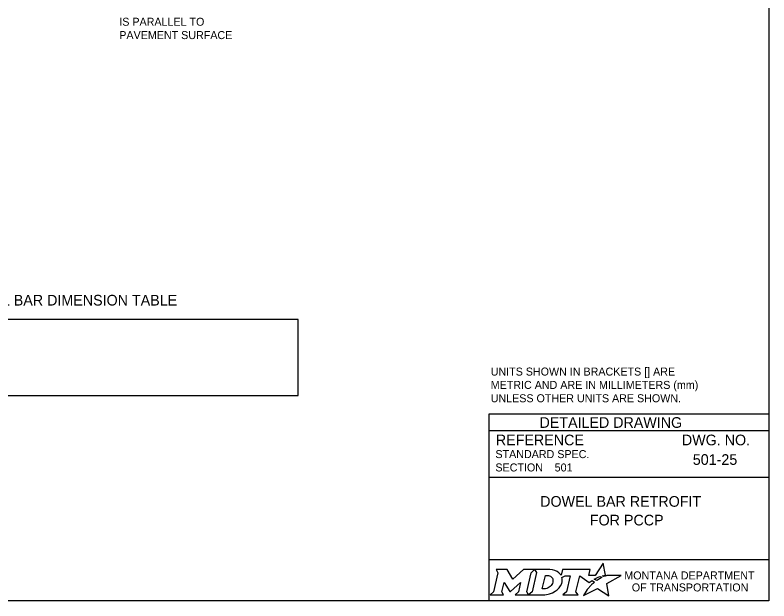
# Model space of a CAD drawing. Extents: x 49991.4 to 50021, y 49987.6 to 50011.4.
# Drawn here: x 50011.1 to 50016.75, y 49987.8 to 49992.19 of the extents above; entities that cross this region are included whole.
import ezdxf

# ---------------------------------------------------------------- set-up
doc = ezdxf.new("R2010")
doc.units = 0
for name, color, linetype in [('Default', 7, 'Continuous'), ('Level 1', 7, 'Continuous'), ('Level 2', 7, 'Continuous'), ('Level 5', 7, 'Continuous')]:
    doc.layers.add(name, color=color, linetype=linetype)

msp = doc.modelspace()

# ---------------------------------------------------------------- linework, layer by layer
at = {"layer": 'Default'}
for points in [[(50015.5126, 49987.9811), (50015.5023, 49987.9867), (50015.5139, 49987.9895), (50015.5255, 49987.9915), (50015.5081, 49988.0816), (50015.4486, 49987.9903), (50015.4013, 49987.9896), (50015.4116, 49988.0337), (50015.2024, 49988.0338), (50015.1923, 49987.9913), (50015.1865, 49987.9996)], [(50014.7056, 49988.0338), (50014.7197, 49988.0104), (50014.6862, 49987.8671), (50014.6605, 49987.8446), (50014.7621, 49987.8446), (50014.7486, 49987.8674), (50014.7648, 49987.9375), (50014.8085, 49987.8685), (50014.8138, 49987.8685), (50014.8889, 49987.938), (50014.8725, 49987.8669), (50014.8478, 49987.8449), (50014.9494, 49987.8449), (50014.9356, 49987.8682), (50014.9688, 49988.0106)], [(50014.9688, 49988.0106), (50014.9941, 49988.0338), (50014.9117, 49988.0338), (50014.8321, 49987.9608), (50014.7876, 49988.0335), (50014.7056, 49988.0338)], [(50015.1077, 49988.0338), (50014.9941, 49988.0338), (50015.0088, 49988.0109), (50014.9749, 49987.8671), (50014.9494, 49987.8449), (50015.06, 49987.8449)], [(50015.1317, 49987.9471), (50015.1305, 49987.939), (50015.1273, 49987.9297), (50015.1231, 49987.9215), (50015.1175, 49987.914), (50015.111, 49987.9071), (50015.1031, 49987.9008), (50015.0948, 49987.8961), (50015.0857, 49987.8922), (50015.0766, 49987.8899), (50015.0674, 49987.889), (50015.0515, 49987.889), (50015.0751, 49987.989), (50015.0911, 49987.989), (50015.0987, 49987.9884), (50015.1063, 49987.9865), (50015.1129, 49987.9835), (50015.119, 49987.9793), (50015.1238, 49987.9743), (50015.1275, 49987.9683), (50015.1302, 49987.9621), (50015.1318, 49987.9547), (50015.1318, 49987.9517), (50015.1317, 49987.9471)], [(50015.1991, 49987.9747), (50015.2237, 49987.9878), (50015.2606, 49987.9878), (50015.232, 49987.8673), (50015.2045, 49987.8446), (50015.3207, 49987.8446), (50015.3037, 49987.8675), (50015.3319, 49987.9877), (50015.4032, 49987.936), (50015.4243, 49987.9511), (50015.444, 49987.9402)], [(50015.3882, 49987.8843), (50015.3729, 49987.8599), (50015.3682, 49987.8524), (50015.3624, 49987.8438), (50015.3601, 49987.8395), (50015.4654, 49987.8926), (50015.5493, 49987.8375), (50015.5362, 49987.9302), (50015.6431, 49987.9886), (50015.5938, 49987.9894), (50015.5637, 49987.9898), (50015.5429, 49987.9901), (50015.5361, 49987.9886), (50015.5312, 49987.9874), (50015.5228, 49987.9851), (50015.5126, 49987.9811)], [(50015.4622, 49987.9535), (50015.4598, 49987.9518), (50015.4415, 49987.9614), (50015.4518, 49987.9671), (50015.4559, 49987.9693), (50015.4645, 49987.9733), (50015.4702, 49987.9759), (50015.4781, 49987.9789), (50015.4854, 49987.9816), (50015.4972, 49987.9742), (50015.4932, 49987.9721), (50015.4886, 49987.9696), (50015.4844, 49987.9674), (50015.4794, 49987.9645), (50015.4775, 49987.9634), (50015.4748, 49987.9618), (50015.4723, 49987.9604), (50015.47, 49987.9588), (50015.4674, 49987.957), (50015.4647, 49987.9552), (50015.4622, 49987.9535)], [(50015.1057, 49987.8522), (50015.1141, 49987.8548), (50015.1271, 49987.8602), (50015.1475, 49987.8712)], [(50015.4021, 49987.9004), (50015.4021, 49987.9004)]]:
    msp.add_lwpolyline(points, dxfattribs=at)
for centre, radius, start, end in [((50015.1308, 49987.9554), 0.0709, 339.5329, 15.8582), ((50015.0868, 49987.9727), 0.1183, 300.9103, 339.1383)]:
    msp.add_arc(centre, radius, start, end, dxfattribs=at)
for centre, major_axis, ratio, start_param, end_param in [((50015.1056, 49987.9864), (0.0834, -0.0037), 0.568097, 0.61298, 1.570796), ((50015.1612, 49987.9937), (0.0361, -0.0295), 0.469099, 1.225588, 1.570796), ((50015.4119, 49987.9106), (-0.0098, -0.0102), 0.016458, 3.141593, 6.279097), ((50015.4329, 49987.9305), (-0.0112, -0.0097), 0.021651, 3.157348, 6.283185), ((50015.3952, 49987.8923), (-0.00694, -0.00806), 0.008222, 0, 3.137361), ((50015.0603, 49987.9932), (0, 0.1484), 0.987302, 3.139398, 3.456847)]:
    msp.add_ellipse(centre, major_axis=major_axis, ratio=ratio, start_param=start_param, end_param=end_param, dxfattribs=at)
at = {"layer": 'Level 1'}
msp.add_lwpolyline([(49999.3835, 49998.9992), (50016.7501, 49998.9992), (50016.7501, 49987.7988), (49999.3835, 49987.7988)], close=True, dxfattribs=at)
at = {"layer": 'Level 2'}
msp.add_lwpolyline([(50009.9559, 49989.3382), (50013.2227, 49989.3382), (50013.2227, 49989.9081), (50009.9559, 49989.9081)], close=True, dxfattribs=at)
at = {"layer": 'Level 5'}
for p, q in [((50016.7501, 49989.1988), (50014.6501, 49989.1988)), ((50014.6501, 49989.1988), (50014.6501, 49987.7988)), ((50016.7501, 49989.0738), (50014.6501, 49989.0738)), ((50016.7501, 49988.7238), (50014.6501, 49988.7238)), ((50016.7501, 49988.1057), (50014.6501, 49988.1057))]:
    msp.add_line(p, q, dxfattribs=at)

# ---------------------------------------------------------------- texts
at = {"layer": 'Default'}
for s, p in [('MONTANA DEPARTMENT', (50015.6663, 49987.96)), ('OF TRANSPORTATION', (50015.7225, 49987.87))]:
    msp.add_text(s, height=0.06, dxfattribs=at).set_placement(p)
at = {"layer": 'Level 2'}
for s, height, p in [('IS PARALLEL TO ', 0.06, (50011.8817, 49992.1104)), ('PAVEMENT SURFACE ', 0.06, (50011.8817, 49992.0104)), ('DOWEL BAR DIMENSION TABLE', 0.08, (50010.6689, 49990.0131)), ('UNITS SHOWN IN BRACKETS [] ARE ', 0.06, (50014.6651, 49989.488)), ('METRIC AND ARE IN MILLIMETERS (mm) ', 0.06, (50014.6651, 49989.388)), ('UNLESS OTHER UNITS ARE SHOWN.', 0.06, (50014.6651, 49989.288)), ('501-25', 0.08, (50016.1798, 49988.8187)), ('501', 0.06, (50015.1444, 49988.7693)), ('DOWEL BAR RETROFIT', 0.08, (50015.0359, 49988.5047)), ('FOR PCCP', 0.08, (50015.408, 49988.3647))]:
    msp.add_text(s, height=height, dxfattribs=at).set_placement(p)
at = {"layer": 'Level 5'}
for s, height, p in [('DETAILED DRAWING', 0.0799, (50015.0311, 49989.0963)), ('REFERENCE', 0.08, (50014.7037, 49988.9654)), ('DWG. NO.', 0.08, (50016.0979, 49988.9654)), ('STANDARD SPEC.', 0.06, (50014.7004, 49988.8694)), ('SECTION', 0.06, (50014.7004, 49988.7694))]:
    msp.add_text(s, height=height, dxfattribs=at).set_placement(p)

doc.saveas('drawing.dxf')
